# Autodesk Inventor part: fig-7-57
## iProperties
Shininess: 77.0
Length Units: 11269
Angle Units: 11279
Time Units: 11290
Mass Units: 11283
Length Display Precision: 3
Angle Display Precision: 2
Created: 2002-01
Part Number: fig-7-57
Document SubType Name: Modeling
Designer: ***
Density: 1 g/cm^3
Density: 0.0
Volumn: 0.0
Area: 0.0
PropertySet Name: Model Information
Control State: 0
Master: False
Checked Out: False
Author: ***
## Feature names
1. Sweep1
